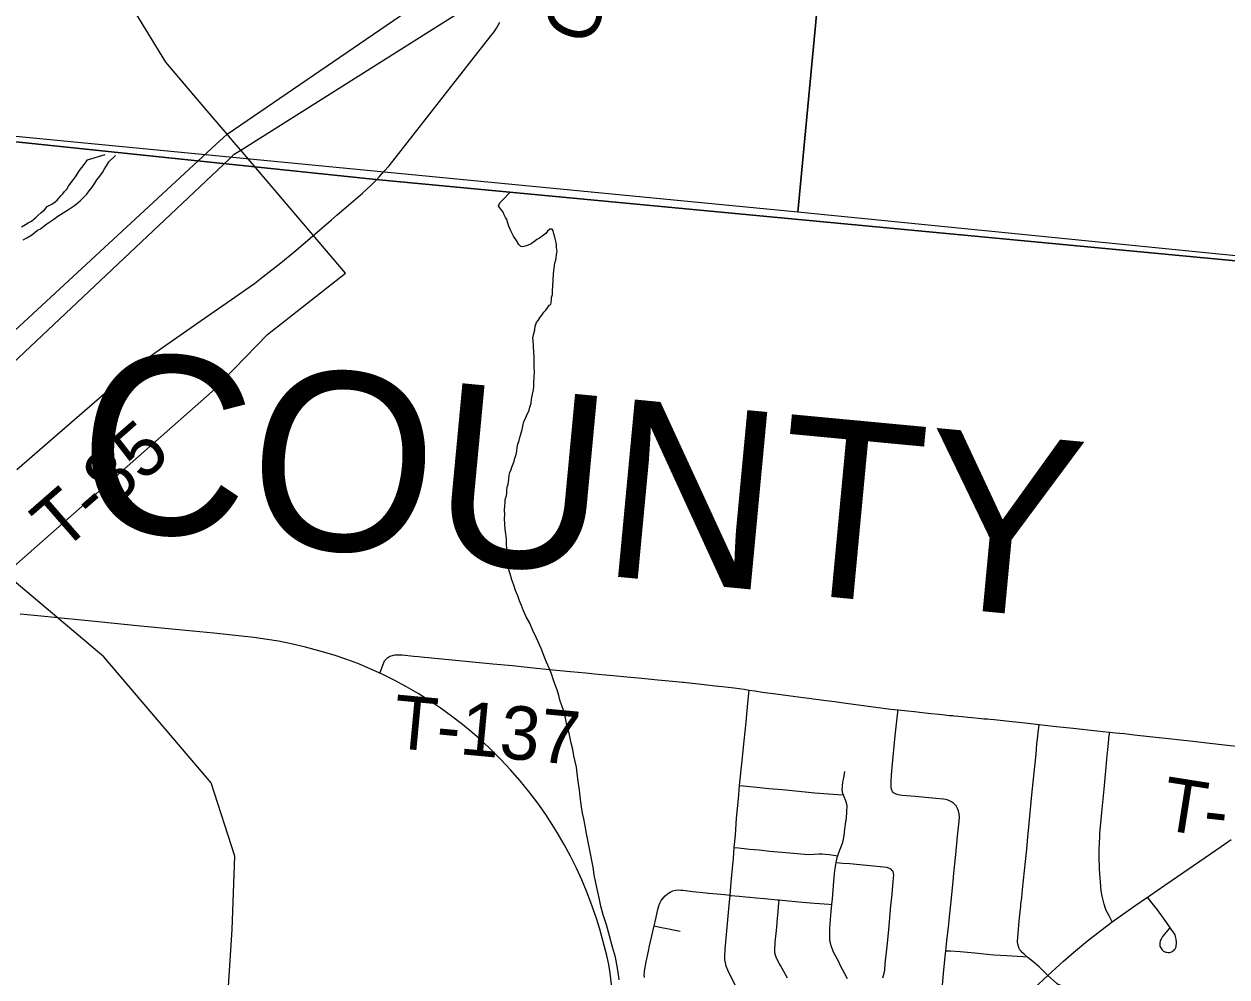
# Model space of a CAD drawing. Extents: x 0 to 1134, y 0 to 440.
# Drawn here: x 212.17 to 250.55, y 56.16 to 86.55 of the extents above; entities that cross this region are included whole.
import ezdxf

# ---------------------------------------------------------------- set-up
doc = ezdxf.new("R2010")
doc.units = 0
for name, color, linetype in [('GM_X_City_Street', 7, 'Continuous'), ('GM_X_County_Road', 7, 'Continuous'), ('GM_X_County_Road_Text', 7, 'Continuous'), ('GM_X_County_Text', 7, 'Continuous'), ('GM_X_Minor_River', 7, 'Continuous'), ('GM_X_Rail_Line', 7, 'Continuous'), ('GM_X_Section', 7, 'Continuous'), ('GM_X_State_Route', 7, 'Continuous'), ('GM_X_Township', 7, 'Continuous'), ('GM_X_Township_Road', 7, 'Continuous'), ('GM_X_Township_Road_Text', 7, 'Continuous'), ('GM_X_Unincorporated', 7, 'Continuous'), ('SH_Cut_Line', 7, 'Continuous')]:
    doc.layers.add(name, color=color, linetype=linetype)

msp = doc.modelspace()

# ---------------------------------------------------------------- linework, layer by layer
at = {"layer": 'GM_X_City_Street'}
for points in [[(235.025, 55.581), (234.714, 56.176), (234.618, 56.379), (234.572, 56.504), (234.544, 56.615), (234.529, 56.71), (234.525, 56.825), (234.537, 57.05), (234.651, 58.33), (234.692, 58.768), (234.743, 59.313), (234.801, 59.944), (234.829, 60.289), (234.862, 60.686), (234.902, 61.225), (234.958, 61.838), (235, 62.27), (235.077, 63.062), (235.139, 63.692), (235.203, 64.285), (235.258, 64.894), (235.303, 65.312)], [(241.429, 55.388), (241.503, 56.277), (241.557, 56.814), (241.577, 56.996), (241.612, 57.313), (241.668, 57.845), (241.692, 58.084), (241.732, 58.469), (241.796, 59.095), (241.846, 59.575), (241.904, 60.167), (241.906, 60.205), (241.925, 60.409), (241.953, 60.649), (242.006, 61.131), (242.013, 61.264), (242.005, 61.361), (241.983, 61.456), (241.954, 61.529), (241.906, 61.614), (241.869, 61.661), (241.826, 61.702), (241.761, 61.748), (241.69, 61.782), (241.616, 61.806), (241.562, 61.818), (241.503, 61.828), (241.26, 61.852), (240.594, 61.915), (240.185, 61.952), (240.059, 61.97), (239.992, 61.988), (239.946, 62.01), (239.906, 62.039), (239.875, 62.077), (239.853, 62.122), (239.837, 62.188), (239.831, 62.259), (239.833, 62.396), (239.845, 62.61), (239.87, 62.85), (239.964, 63.852), (240.039, 64.517), (240.057, 64.678)], [(244.827, 56.212), (244.55, 56.481), (244.354, 56.65), (244.201, 56.774), (244.169, 56.8), (244.074, 56.884), (244.016, 56.941), (243.976, 56.985), (243.957, 57.009), (243.942, 57.029), (243.921, 57.069), (243.906, 57.106), (243.894, 57.138), (243.88, 57.183), (243.872, 57.223), (243.866, 57.268), (243.868, 57.303), (243.875, 57.422), (243.883, 57.554), (243.903, 57.81), (243.927, 58.051), (243.946, 58.235), (243.966, 58.416), (243.974, 58.486), (243.997, 58.699), (244.022, 58.953), (244.118, 59.84), (244.149, 60.136), (244.197, 60.617), (244.227, 60.948), (244.27, 61.407), (244.29, 61.622), (244.309, 61.86), (244.34, 62.175), (244.415, 62.871), (244.456, 63.266), (244.486, 63.6), (244.502, 63.755), (244.532, 64.043), (244.541, 64.112), (244.554, 64.212)], [(246.889, 57.919), (246.785, 58.11), (246.732, 58.208), (246.697, 58.284), (246.672, 58.344), (246.627, 58.486), (246.565, 58.739), (246.534, 58.904), (246.508, 59.182), (246.492, 59.442), (246.482, 59.627), (246.469, 59.978), (246.47, 60.201), (246.478, 60.462), (246.487, 60.61), (246.494, 60.74), (246.509, 60.963), (246.55, 61.407), (246.624, 62.149), (246.689, 62.851), (246.712, 63.103), (246.722, 63.237), (246.743, 63.401), (246.766, 63.631), (246.777, 63.727), (246.783, 63.796), (246.795, 63.897), (246.803, 63.971)], [(238.443, 56.099), (238.201, 56.56), (238.171, 56.627), (238.05, 56.854), (238.008, 56.936), (237.948, 57.071), (237.917, 57.158), (237.895, 57.248), (237.881, 57.321), (237.873, 57.412), (237.873, 57.524), (237.881, 57.717), (237.888, 57.842), (237.902, 57.998), (237.923, 58.247), (237.94, 58.475), (237.957, 58.657), (237.982, 58.926), (238.008, 59.22), (238.039, 59.553), (238.076, 59.807), (238.115, 59.973), (238.129, 60.024), (238.154, 60.097), (238.227, 60.288), (238.276, 60.429), (238.298, 60.508), (238.32, 60.606), (238.344, 60.755), (238.349, 60.787), (238.371, 60.957), (238.376, 61.01), (238.391, 61.132), (238.395, 61.167), (238.404, 61.238), (238.409, 61.292), (238.415, 61.365), (238.423, 61.489), (238.427, 61.56), (238.427, 61.615), (238.421, 61.67), (238.411, 61.705), (238.389, 61.775), (238.334, 61.911), (238.312, 61.967), (238.294, 62.014), (238.282, 62.068), (238.273, 62.141), (238.277, 62.214), (238.279, 62.251), (238.296, 62.38), (238.316, 62.47), (238.331, 62.562), (238.354, 62.717)], [(235, 62.27), (235.117, 62.259), (235.326, 62.239), (235.546, 62.218), (235.933, 62.175), (236.359, 62.136), (236.784, 62.096), (237.394, 62.039), (237.838, 62.001), (238.134, 61.98), (238.312, 61.967)], [(234.829, 60.289), (234.96, 60.276), (235.232, 60.249), (235.323, 60.241), (235.625, 60.211), (235.967, 60.178), (236.596, 60.121), (237.071, 60.08), (237.229, 60.072), (237.524, 60.09), (237.629, 60.087), (237.728, 60.08), (237.857, 60.066), (238.129, 60.024)], [(238.076, 59.807), (238.295, 59.792), (238.518, 59.777), (239.478, 59.687), (239.587, 59.673), (239.68, 59.658), (239.751, 59.64), (239.803, 59.619), (239.834, 59.598)], [(239.565, 56.139), (239.59, 56.211), (239.613, 56.282), (239.629, 56.373), (239.647, 56.577), (239.704, 57.14), (239.756, 57.668), (239.805, 58.187), (239.828, 58.431), (239.864, 58.799), (239.89, 59.082), (239.901, 59.191), (239.912, 59.323), (239.917, 59.408), (239.91, 59.466), (239.892, 59.521), (239.87, 59.558), (239.834, 59.598)], [(231.966, 56.149), (231.956, 56.237), (231.96, 56.284), (231.968, 56.349), (232.021, 56.642), (232.092, 56.988), (232.127, 57.152), (232.274, 57.79), (232.303, 57.916), (232.387, 58.317), (232.416, 58.425), (232.45, 58.512), (232.496, 58.595), (232.555, 58.674), (232.624, 58.747), (232.7, 58.811), (232.783, 58.864), (232.871, 58.906), (232.962, 58.933), (233.044, 58.938), (233.123, 58.933), (233.201, 58.925), (233.495, 58.889), (233.933, 58.843), (234.006, 58.836), (234.281, 58.81), (234.52, 58.787), (234.692, 58.768), (234.722, 58.764), (234.979, 58.74), (235.181, 58.719), (235.328, 58.705), (235.523, 58.687), (235.79, 58.66), (236.202, 58.622), (236.258, 58.617), (236.562, 58.585), (237.001, 58.547), (237.384, 58.516), (237.551, 58.503), (237.849, 58.481), (237.94, 58.475)], [(236.521, 56.118), (236.405, 56.331), (236.305, 56.525), (236.273, 56.585), (236.18, 56.765), (236.143, 56.855), (236.123, 56.931), (236.117, 57.01), (236.137, 57.272), (236.164, 57.551), (236.182, 57.749), (236.207, 58.032), (236.227, 58.239), (236.24, 58.403), (236.258, 58.617)], [(248.717, 57.723), (248.494, 57.447), (248.471, 57.414), (248.444, 57.37), (248.429, 57.336), (248.416, 57.298), (248.408, 57.265), (248.401, 57.21), (248.4, 57.182), (248.404, 57.155), (248.414, 57.12), (248.432, 57.086), (248.453, 57.054), (248.476, 57.028), (248.498, 57.006), (248.52, 56.989), (248.546, 56.976), (248.568, 56.966), (248.596, 56.957), (248.631, 56.95), (248.666, 56.946), (248.695, 56.945), (248.726, 56.946), (248.757, 56.953), (248.779, 56.96), (248.804, 56.972), (248.83, 56.99), (248.853, 57.009), (248.877, 57.033), (248.893, 57.058), (248.901, 57.077), (248.912, 57.1), (248.921, 57.128), (248.93, 57.166), (248.933, 57.222), (248.933, 57.275), (248.926, 57.367), (248.919, 57.408), (248.909, 57.454), (248.889, 57.501), (248.872, 57.536), (248.852, 57.568), (248.767, 57.687), (248.723, 57.747), (248.629, 57.884), (248.522, 58.036), (248.327, 58.299), (248.163, 58.51), (248.01, 58.706)], [(232.274, 57.79), (232.505, 57.742), (232.736, 57.693), (232.892, 57.661), (233.103, 57.62)], [(241.577, 56.996), (241.729, 56.99), (242.038, 56.97), (242.503, 56.929), (243.114, 56.872), (243.522, 56.841), (244.032, 56.809), (244.169, 56.8)], [(244.827, 56.212), (245.103, 55.968), (245.166, 55.929), (245.234, 55.9), (245.288, 55.888), (245.348, 55.883)]]:
    msp.add_lwpolyline(points, dxfattribs=at)
at = {"layer": 'GM_X_County_Road'}
msp.add_lwpolyline([(223.403, 81.573), (223.514, 81.694), (223.65, 81.845), (223.813, 82.03), (225.809, 84.574), (227.029, 86.136), (227.166, 86.308), (227.243, 86.423), (227.297, 86.515), (227.35, 86.612)], dxfattribs=at)
at = {"layer": 'GM_X_Minor_River'}
for points in [[(212.091, 80.079), (212.218, 80.156), (212.298, 80.212), (212.402, 80.267), (212.482, 80.334), (212.54, 80.379), (212.61, 80.446), (212.702, 80.536), (212.817, 80.625), (212.91, 80.738), (213.059, 80.803), (213.163, 80.882), (213.221, 80.938), (213.279, 80.994), (213.348, 81.072), (213.406, 81.14), (213.464, 81.207), (213.534, 81.286), (213.592, 81.376), (213.639, 81.455), (213.72, 81.556), (213.813, 81.68), (213.884, 81.793), (213.942, 81.883), (214.012, 81.973), (214.082, 82.074), (214.151, 82.153), (214.198, 82.221), (214.758, 82.388)], [(212.142, 79.668), (212.257, 79.734), (212.383, 79.812), (212.51, 79.901), (212.602, 79.979), (212.694, 80.023), (212.798, 80.101), (212.901, 80.179), (212.994, 80.246), (213.12, 80.324), (213.247, 80.424), (213.42, 80.536), (213.615, 80.658), (213.776, 80.769), (213.961, 80.914), (214.076, 81.026), (214.169, 81.127), (214.25, 81.229), (214.343, 81.352), (214.425, 81.476), (214.495, 81.578), (214.588, 81.702), (214.67, 81.814), (214.728, 81.916), (214.798, 82.029), (214.869, 82.153), (215.087, 82.357)], [(227.395, 80.64), (227.339, 80.698), (227.306, 80.755), (227.353, 80.846), (227.457, 80.958), (227.658, 81.172)], [(227.522, 71.387), (227.546, 71.478), (227.571, 71.58), (227.572, 71.682), (227.585, 71.785), (227.61, 71.875), (227.635, 72.023), (227.648, 72.16), (227.672, 72.25), (227.708, 72.341), (227.732, 72.42), (227.756, 72.477), (227.803, 72.613), (227.828, 72.704), (227.851, 72.76), (227.876, 72.862), (227.888, 72.942), (227.901, 73.044), (227.926, 73.158), (227.962, 73.271), (227.986, 73.362), (228.022, 73.475), (228.059, 73.623), (228.083, 73.725), (228.119, 73.872), (228.167, 73.974), (228.214, 74.087), (228.249, 74.166), (228.285, 74.234), (228.309, 74.336), (228.345, 74.461), (228.358, 74.586), (228.395, 74.745), (228.42, 74.881), (228.433, 74.995), (228.435, 75.12), (228.449, 75.291), (228.452, 75.462), (228.443, 75.61), (228.446, 75.77), (228.448, 75.929), (228.428, 76.089), (228.411, 76.454), (228.401, 76.534), (228.413, 76.59), (228.437, 76.681), (228.462, 76.795), (228.475, 76.92), (228.522, 77.033), (228.569, 77.101), (228.639, 77.202), (228.697, 77.281), (228.755, 77.36), (228.813, 77.427), (228.872, 77.506), (228.918, 77.585), (228.976, 77.607), (228.988, 77.675), (229.001, 77.755), (229.002, 77.834), (229.026, 77.925), (229.028, 78.039), (229.042, 78.198), (229.045, 78.38), (229.059, 78.585), (229.099, 78.938), (229.135, 79.017), (229.147, 79.096), (229.16, 79.199), (229.173, 79.301), (229.163, 79.358), (229.152, 79.427), (229.154, 79.518), (229.133, 79.632), (229.101, 79.758), (229.068, 79.861), (229.047, 79.953), (229.014, 80.01), (228.945, 80.011), (228.865, 79.944), (228.818, 79.877), (228.703, 79.787), (228.61, 79.72), (228.53, 79.676), (228.461, 79.632), (228.346, 79.542), (228.254, 79.498), (228.162, 79.466), (228.071, 79.444), (228.014, 79.457), (227.958, 79.526), (227.88, 79.652), (227.78, 79.791), (227.703, 79.952), (227.637, 80.101), (227.604, 80.204), (227.572, 80.318), (227.528, 80.387), (227.483, 80.468), (227.45, 80.548), (227.395, 80.64)], [(231.152, 56.072), (231.132, 56.243), (231.101, 56.437), (231.038, 56.792), (230.941, 57.112), (230.844, 57.478), (230.747, 57.822), (230.65, 58.142), (230.574, 58.417), (230.522, 58.68), (230.468, 58.92), (230.415, 59.16), (230.362, 59.423), (230.321, 59.663), (230.194, 60.315), (230.152, 60.52), (230.11, 60.738), (230.068, 60.978), (230.026, 61.206), (229.984, 61.389), (229.952, 61.583), (229.932, 61.743), (229.912, 61.914), (229.893, 62.12), (229.852, 62.405), (229.821, 62.645), (229.79, 62.851), (229.748, 63.034), (229.705, 63.217), (229.674, 63.411), (229.62, 63.617), (229.578, 63.834), (229.536, 64.028), (229.481, 64.189), (229.45, 64.36), (229.408, 64.589), (229.342, 64.783), (229.277, 64.955), (229.234, 65.138), (229.18, 65.322), (229.114, 65.482), (229.049, 65.654), (228.995, 65.826), (228.918, 66.009), (228.841, 66.204), (228.753, 66.411), (228.666, 66.64), (228.523, 66.962), (228.402, 67.214), (228.303, 67.444), (228.192, 67.65), (228.104, 67.834), (228.038, 68.006), (227.972, 68.155), (227.918, 68.316), (227.852, 68.488), (227.798, 68.659), (227.732, 68.831), (227.678, 69.015), (227.635, 69.141), (227.614, 69.278), (227.582, 69.392), (227.573, 69.529), (227.575, 69.654), (227.559, 70.122), (227.539, 70.293), (227.519, 70.441), (227.51, 70.601), (227.501, 70.772), (227.503, 70.909), (227.494, 71.046), (227.508, 71.182), (227.521, 71.296), (227.522, 71.387)]]:
    msp.add_lwpolyline(points, dxfattribs=at)
at = {"layer": 'GM_X_Rail_Line'}
for p, q in [((219.382, 82.177), (219.083, 82.528)), ((222.429, 78.605), (219.382, 82.177))]:
    msp.add_line(p, q, dxfattribs=at)
for points in [[(218.648, 83.037), (217.883, 83.933), (216.691, 85.332), (215.218, 87.758), (215.044, 89.058), (215.997, 90.271), (218.076, 91.484), (219.982, 93.131), (221.022, 95.038), (221.282, 97.031), (220.935, 97.724), (218.769, 98.677), (221.544, 132.36), (223.618, 133.946), (235.537, 142.526)], [(218.648, 83.037), (235.81, 94.775), (255.549, 106.729), (261.683, 110.193), (266.302, 112.35), (271.641, 114.346)], [(219.083, 82.528), (255.537, 105.523), (261.361, 108.742), (267.318, 112.049), (271.641, 114.346)], [(217.865, 82.321), (218.288, 82.712), (218.648, 83.037)], [(219.083, 82.528), (218.866, 82.782), (218.648, 83.037)], [(218.71, 82.241), (218.877, 82.399), (219.083, 82.528)], [(151.357, 17.107), (165.007, 29.729), (205.893, 71.252), (217.865, 82.321)], [(153.633, 17.107), (203.787, 68.18), (218.71, 82.241)], [(204.659, 17.107), (213.552, 20.586), (215.209, 21.415), (216.984, 36.987), (218.344, 50.421), (218.813, 57.67), (218.896, 60.013), (218.144, 62.355), (214.715, 66.37), (211.574, 69.017), (218.175, 74.838), (219.935, 76.648), (222.429, 78.605)]]:
    msp.add_lwpolyline(points, dxfattribs=at)
at = {"layer": 'GM_X_Section'}
for points in [[(239.744, 111.129), (236.861, 80.551), (207.062, 83.429), (209.686, 113.866)], [(239.744, 111.129), (270.808, 108.206), (267.778, 77.468), (236.861, 80.551)]]:
    msp.add_lwpolyline(points, close=True, dxfattribs=at)
at = {"layer": 'GM_X_State_Route'}
for points in [[(230.764, 56.845), (230.535, 57.683), (230.419, 58.056), (230.256, 58.531), (230.116, 58.896), (229.964, 59.255), (229.792, 59.627), (229.6, 60.009), (229.396, 60.385), (229.174, 60.773), (229.019, 61.027), (228.815, 61.338), (228.558, 61.702), (228.278, 62.074), (227.996, 62.42), (227.69, 62.77), (227.385, 63.096), (227.082, 63.398), (226.77, 63.691), (226.462, 63.961), (226.161, 64.208), (225.807, 64.481), (225.445, 64.742), (225.09, 64.981), (224.743, 65.198), (224.373, 65.413), (223.98, 65.625), (223.597, 65.815), (223.515, 65.853), (223.208, 65.993), (222.813, 66.157), (222.465, 66.288), (222.059, 66.422), (221.577, 66.565), (221.146, 66.68), (220.693, 66.786), (220.292, 66.867), (219.925, 66.927), (219.501, 66.984), (218.222, 67.123), (217.11, 67.237), (215.774, 67.361), (214.642, 67.474), (212.713, 67.663), (212.05, 67.731)], [(248.569, 59.087), (249.138, 59.479), (250.36, 60.323), (250.681, 60.542)], [(243.076, 54.515), (243.181, 54.614), (243.903, 55.314), (244.391, 55.802), (244.827, 56.212), (245.327, 56.662), (245.65, 56.944), (246.096, 57.312), (246.522, 57.645), (246.889, 57.919), (246.955, 57.968), (247.574, 58.404), (248.01, 58.706), (248.077, 58.752), (248.569, 59.087)], [(230.853, 52.469), (230.875, 52.618), (230.908, 52.833), (230.944, 53.165), (230.974, 53.573), (230.987, 53.852), (230.998, 54.242), (230.996, 54.67), (230.985, 55.041), (230.959, 55.487), (230.926, 55.836), (230.895, 56.097), (230.871, 56.281), (230.821, 56.554), (230.764, 56.845)]]:
    msp.add_lwpolyline(points, dxfattribs=at)
at = {"layer": 'GM_X_Township'}
msp.add_lwpolyline([(335.783, 70.994), (282.056, 76.051), (277.938, 76.439), (271.82, 77.017), (271.49, 77.048), (270.873, 77.107), (270.427, 77.153), (267.348, 77.44), (223.396, 81.589), (203.056, 83.725), (203.598, 83.809), (204.339, 84.291), (206.29, 84.511), (207.274, 85.494), (207.765, 86.254), (208.481, 87.014)], dxfattribs=at)
at = {"layer": 'GM_X_Township_Road'}
for points in [[(211.942, 72.35), (212.986, 73.253), (214.575, 74.636), (215.183, 75.158), (215.586, 75.488), (215.968, 75.785), (216.373, 76.083), (217.824, 77.098), (218.376, 77.478), (218.792, 77.762), (218.899, 77.837), (219.355, 78.162), (219.521, 78.282), (219.788, 78.487), (220.359, 78.937), (220.777, 79.281), (221.133, 79.581), (221.46, 79.859), (221.74, 80.104), (221.98, 80.311), (222.163, 80.469), (222.446, 80.711), (222.97, 81.161), (223.259, 81.426), (223.403, 81.573)], [(223.515, 65.853), (223.638, 66.157), (223.661, 66.215), (223.674, 66.241), (223.697, 66.274), (223.733, 66.311), (223.779, 66.349), (223.807, 66.37), (223.847, 66.39), (223.877, 66.403), (223.922, 66.418), (223.959, 66.426), (223.999, 66.433), (224.04, 66.438), (224.095, 66.439), (224.167, 66.438), (224.228, 66.433), (224.6, 66.393), (224.748, 66.38), (224.841, 66.371), (225.825, 66.276), (226.475, 66.214), (227.125, 66.153), (227.756, 66.093), (228.219, 66.045), (228.922, 65.969), (229.605, 65.899), (230.087, 65.856), (230.366, 65.83), (230.959, 65.771), (231.405, 65.732), (231.776, 65.698), (232.389, 65.639), (232.852, 65.595), (233.175, 65.564)], [(233.175, 65.564), (233.205, 65.562), (233.784, 65.496), (234.219, 65.449), (234.452, 65.423), (234.63, 65.403), (234.826, 65.379), (235.146, 65.335), (235.303, 65.312)], [(235.303, 65.312), (235.485, 65.286), (235.733, 65.248), (236.155, 65.192), (236.548, 65.141), (237.024, 65.076), (237.216, 65.05), (237.347, 65.031), (237.602, 64.999), (237.751, 64.98), (238.038, 64.942), (238.244, 64.915), (238.399, 64.892), (239.264, 64.775), (239.818, 64.705), (240.057, 64.678)], [(240.057, 64.678), (240.167, 64.666), (240.358, 64.648), (240.573, 64.624), (240.823, 64.597), (241.108, 64.566), (241.355, 64.539), (241.465, 64.527), (241.687, 64.505), (241.797, 64.496), (241.841, 64.491), (241.983, 64.474), (242.101, 64.464), (242.278, 64.445), (242.414, 64.433), (242.619, 64.412), (242.718, 64.403), (242.792, 64.396), (242.907, 64.389), (242.995, 64.38), (243.119, 64.369), (243.596, 64.317), (244.096, 64.262), (244.554, 64.212)], [(244.554, 64.212), (245.004, 64.163), (245.635, 64.1), (246.394, 64.013), (246.803, 63.971)], [(246.803, 63.971), (246.988, 63.952), (247.266, 63.922), (247.586, 63.884), (248.077, 63.826), (248.791, 63.753), (248.969, 63.733)], [(248.969, 63.733), (249.454, 63.682), (249.9, 63.633), (250.569, 63.554), (250.959, 63.51), (250.989, 63.508)]]:
    msp.add_lwpolyline(points, dxfattribs=at)
at = {"layer": 'GM_X_Unincorporated'}
msp.add_lwpolyline([(335.783, 70.994), (282.056, 76.051), (277.938, 76.439), (271.82, 77.017), (271.49, 77.048), (270.873, 77.107), (270.427, 77.153), (267.348, 77.44), (223.396, 81.589), (203.056, 83.725)], dxfattribs=at)
at = {"layer": 'SH_Cut_Line'}
for points in [[(191.505, 262.177), (186.299, 206.946), (186.171, 205.401), (184.337, 184.605), (184.291, 183.936), (180.952, 146.735), (180.65, 140.913), (178.666, 119.298), (178.473, 116.876), (178.429, 116.408), (178.401, 116.166), (178.274, 114.839), (176.426, 95.74), (175.597, 86.381), (203.056, 83.725), (223.396, 81.589), (267.348, 77.44), (270.427, 77.153), (270.873, 77.107), (271.49, 77.048), (271.82, 77.017), (277.938, 76.439), (282.056, 76.051), (335.783, 70.994)], [(335.783, 70.994), (282.056, 76.051), (277.938, 76.439), (271.82, 77.017), (271.49, 77.048), (270.873, 77.107), (270.427, 77.153), (267.348, 77.44), (223.396, 81.589), (203.056, 83.725)]]:
    msp.add_lwpolyline(points, dxfattribs=at)

# ---------------------------------------------------------------- texts
at = {"layer": 'GM_X_County_Road_Text'}
msp.add_text('C', height=1.705, rotation=68.6041, dxfattribs=at).set_placement((230.215, 85.78))
at = {"layer": 'GM_X_County_Text'}
msp.add_text('GREENE COUNTY', height=5.68182, rotation=354.6158, dxfattribs=at).set_placement((179.644, 73.772))
at = {"layer": 'GM_X_Township_Road_Text'}
for s, height, rotation, p in [('T-85', 1.7045, 41.0184, (213.369, 69.68)), ('T-137', 1.7045, 354.6106, (223.889, 63.474)), ('T', 1.705, 350.9889, (248.392, 60.877)), ('-', 1.705, 353.8492, (249.743, 60.665))]:
    msp.add_text(s, height=height, rotation=rotation, dxfattribs=at).set_placement(p)

doc.saveas('drawing.dxf')
